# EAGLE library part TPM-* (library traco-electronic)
DC/DC Konverter 10/15 Watt, 1 x Input, 2 x Output Suurce: http://www.tracopower.com/datasheet_g/tpm-d.pdf
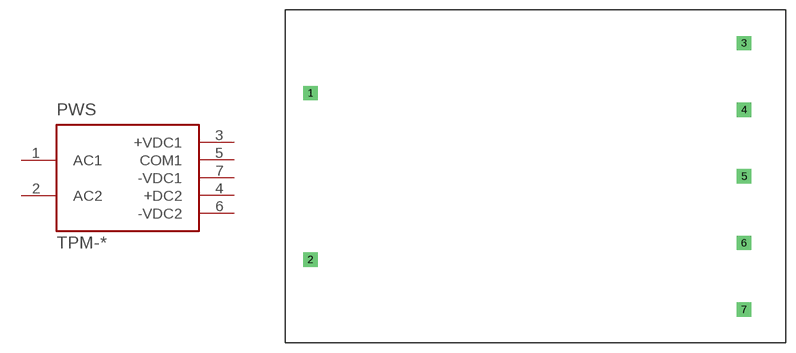
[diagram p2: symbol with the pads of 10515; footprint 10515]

Designator prefix PWS

## TPM-05212 (OC_FARNELL: unknown; OC_NEWARK: unknown), TPM-05215 (OC_FARNELL: unknown; OC_NEWARK: unknown)  [10515]
1  AC1  in
2  AC2  in
3  +VDC1  pas
4  +DC2  pas
5  COM1  pas
6  -VDC2  pas
7  -VDC1  pas

## Footprint 10515 (pad centres in mm)
drill 1.27 pad 2.184 square: 1 3.81,38.1; 2 3.81,12.7; 3 69.85,45.72; 4 69.85,35.56; 5 69.85,25.4; 6 69.85,15.24; 7 69.85,5.08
